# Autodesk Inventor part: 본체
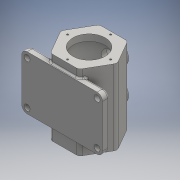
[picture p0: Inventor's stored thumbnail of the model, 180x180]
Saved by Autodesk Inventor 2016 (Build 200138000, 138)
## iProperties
Created: 2021-06
Part Number: 본체
Material: 일반
Document SubType Name: Modeling
Designer: pc-04
Density: 1 g/cm^3
Appearance: 기본값
Author: pc-04
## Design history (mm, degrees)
sketch "스케치1"
  geometry: L1 (75, -50)-(-75, -50); L2 (-75, -50)-(-75, 50); L3 (-75, 50)-(75, 50); L4 (75, 50)-(75, -50); L5 (75, -50)-(-75, 50); L6 (-75, -50)-(75, 50); 1 further point
  constraints: 12 end point, 2 midpoint, 2 parallel, 1 horizontal, 1 perpendicular
  dimensions: "d0" = 150 distance of L2.end L3.end; "d1" = 100 distance of L1.end L2.end
extrude "돌출1" new body sketch "스케치1" distance "d2" = 12; taper "d3" = 0 deg
fillet "모깎기1" dims "d4" = 10
sketch "스케치2"
  geometry: A1 r 10 centre (65, -40) between (65, -50) and (75, -40) reference; A2 r 10 centre (65, 40) between (75, 40) and (65, 50) reference; A3 r 10 centre (-65, 40) between (-65, 50) and (-75, 40) reference; A4 r 10 centre (-65, -40) between (-75, -40) and (-65, -50) reference; 1 further point
hole "구멍1" sketch "스케치2" at (-65, -40), (-65, 40), (65, -40), (65, 40) diameter "d5" = 11; stored, may be unused: countersink angle "d9" = 90 deg, drill point angle "d11" = 118 deg; dims "d6" = 6, "d7" = 4, "d8" = 2, "d10" = 8
sketch "스케치3" dims "d13" = 105
  geometry: L1 (0, 0)-(0, 50); L2 (-52.5, 50)-(-26.25, 95.466); L3 (-26.25, 95.466)-(26.25, 95.466); L4 (26.25, 95.466)-(52.5, 50); L5 (52.5, 50)-(26.25, 4.534); L6 (26.25, 4.534)-(-26.25, 4.534); L7 (-26.25, 4.534)-(-52.5, 50); 2 further points
  constraints: 14 end point, 2 coincident, 1 horizontal alignment, 1 vertical, 15 other
  dimensions: "d12" = 50 distance of L1.start L1.end
extrude "돌출2" join sketch "스케치3" distance "d14" = 75; taper "d15" = 0 deg
extrude "돌출3" join sketch "스케치3" distance "d16" = 65; taper "d17" = 0 deg
node "작업 평면1"
sketch "스케치4"
  geometry: L1 (52.5, 50)-(26.25, 95.466) reference; L2 (26.25, 95.466)-(-26.25, 95.466) reference; L3 (-26.25, 95.466)-(-52.5, 50) reference; L4 (-52.5, 50)-(-26.25, 4.534) reference; L5 (-26.25, 4.534)-(26.25, 4.534) reference; L6 (26.25, 4.534)-(52.5, 50) reference; L7 (52.5, 50)-(-52.5, 50); L8 (0, 95.466)-(0, 4.534); C1 r 37.5 at (0, 50); 1 further point
  constraints: 4 end point, 3 midpoint, 1 centre point, 1 horizontal
  dimensions: "d18" = 75 diameter of C1
extrude "돌출4" cut sketch "스케치4" stored distance "d19" = 116; taper "d20" = 0 deg
node "작업 평면2"
sketch "스케치5"
  geometry: C1 r 37.5 at (0, 50) reference; C2 r 30 at (0, 50); 1 further point
  constraints: 1 centre point, 1 coincident
  dimensions: "d22" = 60 diameter of C2
extrude "돌출5" cut sketch "스케치5" distance "d23" = 12; taper "d24" = 0 deg
sketch "스케치6"
  geometry: L1 (26.25, -75)-(26.25, -45); L2 (26.25, -75)-(26.25, -105); C1 r 12.5 at (26.25, -45); C2 r 15 at (26.25, -45); C3 r 20 at (26.25, -45); C4 r 12.5 at (26.25, -105); C5 r 15 at (26.25, -105); C6 r 20 at (26.25, -105)
  constraints: 6 centre point, 6 coincident, 4 end point, 1 point on line, 1 vertical
  dimensions: "d25" = 30 distance of L1.start L1.end; "d26" = 30 distance of L1.start L2.end; "d27" = 25 diameter of C1; "d28" = 30 diameter of C2; "d29" = 40 diameter of C3; "d30" = 25 diameter of C4; "d31" = 30 diameter of C5; "d32" = 40 diameter of C6
extrude "돌출6" join sketch "스케치6" distance "d33" = 8; taper "d34" = 0 deg
extrude "돌출7" cut sketch "스케치6" stored distance "d35" = 8; taper "d36" = 0 deg
sketch "스케치7"
  geometry: L1 (0, 50)-(0, 90); C1 r 30 at (0, 50) reference; 1 further point
  constraints: 2 end point, 1 coincident, 1 vertical
hole "구멍2" sketch "스케치7" at (0, 90) diameter "d38" = 3.242; stored, may be unused: countersink angle "d42" = 90 deg, drill point angle "d44" = 118 deg; dims "d39" = 8, "d40" = 4, "d41" = 2, "d43" = 10
sketch "스케치8"
  geometry: L1 (0, 50)-(-28.284, 78.284); C1 r 30 at (0, 50) reference; C2 r 40 at (0, 50); 1 further point
  constraints: 2 end point, 1 centre point, 1 coincident
  dimensions: "d48" = 80 diameter of C2
hole "구멍3" sketch "스케치8" at (-28.284, 78.284) diameter "d49" = 3.242; stored, may be unused: countersink angle "d53" = 90 deg, drill point angle "d55" = 118 deg; dims "d50" = 8, "d51" = 4, "d52" = 2, "d54" = 10
fillet "모깎기2" dims "d59" = 3, "d60" = 8, "d61" = 5
node "솔리드1"
mirror "대칭1"
pattern_circular "원형 패턴1" dims angle "d46" = 360 deg
pattern_circular "원형 패턴2" dims angle "d57" = 360 deg
node "투영된 루프1"
other parameters: "d21" = 58
